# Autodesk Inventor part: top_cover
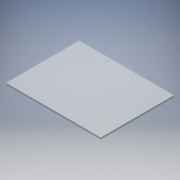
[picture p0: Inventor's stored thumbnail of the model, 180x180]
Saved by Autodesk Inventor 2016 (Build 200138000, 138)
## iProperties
Created: 2015-11
Part Number: top_cover
Material: Generic
Document SubType Name: Modeling
Designer: t_silvdo
Density: 1 g/cm^3
Appearance: Default
Author: t_silvdo
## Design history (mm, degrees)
sketch "Sketch1"
  geometry: L1 (0, 0)-(279.4, 0); L2 (279.4, 0)-(279.4, -215.9); L3 (279.4, -215.9)-(0, -215.9); L4 (0, -215.9)-(0, 0)
  constraints: 8 end point, 2 parallel, 1 horizontal, 1 perpendicular
  dimensions: "d0" = 279.4 distance of L2.end L3.end; "d1" = 215.9 distance of L1.end L2.end
extrude "Extrusion1" new body sketch "Sketch1" distance "d2" = 4.7625; taper "d3" = 0 deg
body "Solid1"
